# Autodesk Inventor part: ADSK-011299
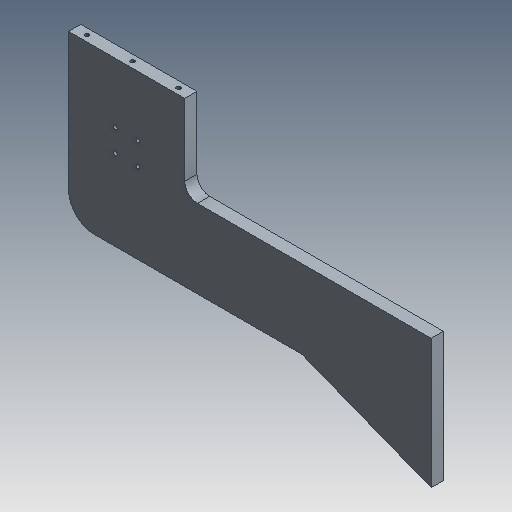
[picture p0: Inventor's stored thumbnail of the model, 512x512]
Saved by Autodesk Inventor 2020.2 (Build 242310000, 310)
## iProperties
Created: 1999-12
Part Number: ADSK-011299
Material: Pearson Aluminium
Document SubType Name: Modeling
Designer: sspink
Density: 2.71 g/cm^3
Appearance: Pearson-Aluminum
Mass: 1295.46 g
Surface Area: 939.34 cm^2
Volume: 478.029 cm^3
Control State: 0
Master: False
Checked Out: False
Shininess: 35.0
Length Units: 11269
Angle Units: 11279
Time Units: 11290
Mass Units: 11283
Length Display Precision: 3
Angle Display Precision: 2
Compacted: True
Cutlength: 8.25 X 14.00 (116 SI)
Material Desc: SHEET,ALUM,0.50
Material_number: A101291
Dimensions: 210x12x356 mm
Mass: 1,295 kg
DocNumber: ADSK-011299.ipt
Folder: 01 - Themengebiete\Simplification\01 - Packaging machine\
VDS_Category: 3D Komponenten
VLT_Material: Pearson Aluminium
Density: 2.71
Volumn: 499.81901910393276
Area: 951.0588557024687
PropertySet Name: Model Information
Author: sspink
Revision Number: -
Title: plate
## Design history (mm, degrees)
derived "ADSK-011298.ipt"
feature "Solide1::ADSK-011298.ipt" dims "d44" = 10
node "Volumenkörper2"
tag "Bezeichnung1"
node "Solide1"
node "Corps solides"
node "Corps surfaciques"
